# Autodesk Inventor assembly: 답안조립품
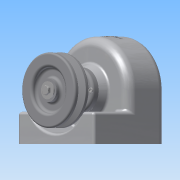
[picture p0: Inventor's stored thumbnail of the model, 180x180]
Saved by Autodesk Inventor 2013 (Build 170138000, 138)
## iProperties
Created: 2015-02
Part Number: 답안조립품
Document SubType Name: Assembly
Designer: Administrator
Author: Administrator
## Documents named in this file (14)
- C:\Documents and Settings\Administrator\바탕 화면\450214V1009\답안조립품.iam
- C:\Documents and Settings\Administrator\바탕 화면\450214V1009\1-본체.ipt
- C:\Documents and Settings\Administrator\바탕 화면\450214V1009\베어링 6001.ipt
- C:\Documents and Settings\Administrator\바탕 화면\450214V1009\축.ipt
- C:\Documents and Settings\Administrator\바탕 화면\450214V1009\5-스퍼기어.ipt
- C:\Documents and Settings\Administrator\바탕 화면\450214V1009\키5x5.ipt
- C:\Documents and Settings\Administrator\바탕 화면\450214V1009\키4x4.ipt
- C:\Documents and Settings\Administrator\바탕 화면\450214V1009\축커버.ipt
- C:\Documents and Settings\Administrator\바탕 화면\450214V1009\오일실.ipt
- C:\Documents and Settings\Administrator\바탕 화면\450214V1009\M3x0.5.ipt
- C:\Documents and Settings\Administrator\바탕 화면\450214V1009\4-벨트풀리.ipt
- C:\Documents and Settings\Administrator\바탕 화면\450214V1009\와샤.ipt
- C:\Documents and Settings\Administrator\바탕 화면\450214V1009\M5x0.8.ipt
- M5x0.8.ipt
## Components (7 placed, 4 different names)
1. 1-본체:1
2. 4-벨트풀리:1 — 각도:4
3. M5x0.8:1
4. M3x0.5:1
5. M3x0.5:2
6. M3x0.5:3
7. M3x0.5:4
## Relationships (1: Angle 1)
- 각도:4 [Angle]: 4-벨트풀리:1
